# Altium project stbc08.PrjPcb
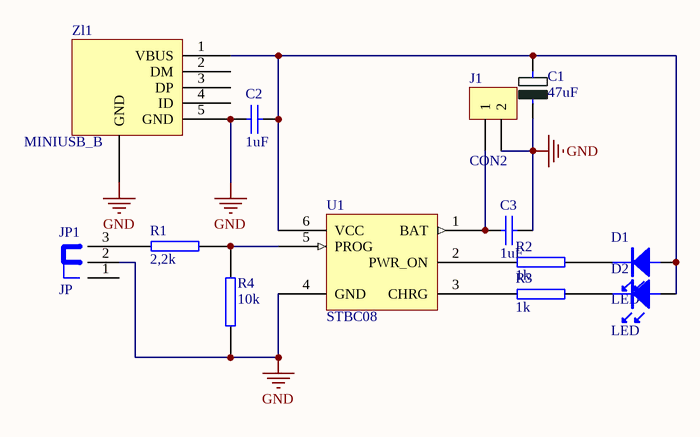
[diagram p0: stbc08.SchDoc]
1 sheet, 13 parts. Net scope: global (net labels, ports and power ports of the same name join across sheets).
Board file: stbc08.PcbDoc

## Sheet stbc08.SchDoc
size A4

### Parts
C1  47uF  [CE_SMD_SIZE_D]
C2  1uF  [0805]
C3  1uF  [0805]
D1  LED  [1206_LED]
D2  LED  [1206_LED]
J1  CON2  [ARK2]
JP1  JP  [sip-3]
R1  2,2k  [0805]
R2  1k  [0805]
R3  1k  [0805]
R4  10k  [0805]
U1  STBC08  [DFN6_3x3]
Zl1  MINIUSB_B  [MiniUSB_B]

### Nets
GND: C1.2(MINUS) C2.1 C3.2 J1.2 JP1.2 R4.1 U1.4(GND) Zl1.0(GND) Zl1.5(GND)
NetC1_1: C1.1(PLUS) C2.2 D1.1(A) D2.1(A) U1.6(VCC) Zl1.1(VBUS)
NetC3_1: C3.1 J1.1 U1.1(BAT)
NetD1_2: D1.2(K) R2.2
NetD2_2: D2.2(K) R3.2
NetJP1_3: JP1.3 R1.1
NetR1_2: R1.2 R4.2 U1.5(PROG)
NetR2_1: R2.1 U1.2(PWR_ON)
NetR3_1: R3.1 U1.3(CHRG)

Not connected (* = marked no-connect by the designer): JP1 1; Zl1 2(DM) 3(DP) 4(ID)

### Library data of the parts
C1 = CP: Capacitor
C2 C3 = Cap: Capacitor
J1 = CON2: Connector
JP1 = JP: Jumper
R1-R4 = RES2
U1 = STBC08PMQ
